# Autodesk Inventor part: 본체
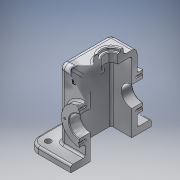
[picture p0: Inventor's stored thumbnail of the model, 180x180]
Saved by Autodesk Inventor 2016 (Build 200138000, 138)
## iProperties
Created: 2022-11
Part Number: 본체
Material: 알루미늄 6061
Document SubType Name: Modeling
Designer: CAD2
Density: 2.7 g/cm^3
Appearance: 알루미늄 - 평지
Mass: 1116.9 g
Surface Area: 1009.84 cm^2
Volume: 413.665 cm^3
Author: CAD2
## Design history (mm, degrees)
sketch "스케치1"
  geometry: L1 (-40, 40)-(40, 40); L2 (40, 40)-(40, -40); L3 (40, -40)-(-40, -40); L4 (-40, -40)-(-40, 40); L5 (-40, 40)-(40, -40); L6 (40, 40)-(-40, -40); 1 further point
  constraints: 12 end point, 2 midpoint, 2 parallel, 1 horizontal, 1 perpendicular
  dimensions: "d0" = 80 distance of L2.end L3.end; "d1" = 80 distance of L1.end L2.end
extrude "돌출1" new body sketch "스케치1" stored distance "d2" = 117; taper "d3" = 0 deg
fillet "모깎기1" dims "d4" = 8
fillet "모깎기2" dims "d5" = 8
feature "쉘1" dims "d6" = 8
fillet "모깎기3" dims "d11" = 3
fillet "모깎기4" dims "d12" = 3
sketch "스케치4"
  geometry: L1 (64, 0)-(0, 0) reference; C1 r 16 at (32, 55); 2 further points
  constraints: 1 centre point, 1 midpoint, 1 vertical alignment
  dimensions: "d13" = 32 diameter of C1; "d14" = 55 distance from line of L1 C1.centre
extrude "돌출3" cut sketch "스케치4" stored distance "d15" = 10; taper "d16" = 0 deg
sketch "스케치5"
  geometry: C1 r 16 at (32, 55) reference; C2 r 27.5 at (32, 55); 1 further point
  constraints: 1 centre point, 1 coincident
  dimensions: "d17" = 55 diameter of C2
extrude "돌출4" join sketch "스케치5" distance "d18" = 9; taper "d19" = 0 deg
sketch "스케치6"
  geometry: C1 r 16 at (32, -55) reference; C2 r 27.5 at (32, -55); 1 further point
  constraints: 1 centre point, 1 coincident
  dimensions: "d20" = 55 diameter of C2
extrude "돌출5" join sketch "스케치6" distance "d21" = 9; taper "d22" = 0 deg
sketch "스케치7"
  geometry: L1 (32, -54)-(-32, -54) reference; L2 (32, 55)-(32, -54) reference; L3 (-32, 55)-(32, 55) reference; L4 (-32, -54)-(-32, 55) reference; C1 r 27.5 at (0, 0) reference; 2 further points
  dimensions: "d23" = 22.5 distance of C1.centre point (0, -22.5)
hole "구멍1" sketch "스케치7" at (0, -22.5) diameter "d24" = 3.242; stored, may be unused: countersink angle "d28" = 90 deg, drill point angle "d30" = 118 deg; dims "d25" = 8, "d26" = 4, "d27" = 2, "d29" = 10
node "작업 평면1"
sketch "스케치8"
  geometry: L1 (-65, 62)-(65, 62); L2 (65, 62)-(65, -62); L3 (65, -62)-(-65, -62); L4 (-65, -62)-(-65, 62); L5 (-65, 62)-(65, -62); L6 (65, 62)-(-65, -62); 1 further point
  constraints: 12 end point, 2 midpoint, 2 parallel, 1 horizontal, 1 perpendicular
  dimensions: "d35" = 130 distance of L2.end L3.end; "d36" = 124 distance of L1.end L2.end
extrude "돌출6" join sketch "스케치8" distance "d37" = 10; taper "d38" = 0 deg
fillet "모깎기5" dims "d39" = 15
hole "구멍2" diameter "d42" = 9; stored, may be unused: countersink angle "d46" = 90 deg, drill point angle "d48" = 0 deg; dims "d40" = 10, "d41" = 10, "d43" = 8, "d44" = 4, "d45" = 2, "d47" = 10
hole "구멍3" diameter "d51" = 9; stored, may be unused: countersink angle "d55" = 90 deg, drill point angle "d57" = 0 deg; dims "d49" = 10, "d50" = 10, "d52" = 8, "d53" = 4, "d54" = 2, "d56" = 10
hole "구멍4" diameter "d60" = 9; stored, may be unused: countersink angle "d64" = 90 deg, drill point angle "d66" = 0 deg; dims "d58" = 10, "d59" = 10, "d61" = 8, "d62" = 4, "d63" = 2, "d65" = 10
hole "구멍5" diameter "d69" = 9; stored, may be unused: countersink angle "d73" = 90 deg, drill point angle "d75" = 0 deg; dims "d67" = 10, "d68" = 10, "d70" = 8, "d71" = 4, "d72" = 2, "d74" = 10
fillet "모깎기6" dims "d76" = 3
sketch "스케치10"
  geometry: L1 (-32, 29)-(-32, -29) reference; L2 (29, 32)-(-29, 32) reference; L3 (32, -29)-(32, 29) reference; L4 (-29, -32)-(29, -32) reference; A1 r 3 centre (-29, -29) between (-32, -29) and (-29, -32) reference; A2 r 3 centre (-29, 29) between (-29, 32) and (-32, 29) reference; A3 r 3 centre (29, 29) between (32, 29) and (29, 32) reference; A4 r 3 centre (29, -29) between (29, -32) and (32, -29) reference; 1 further point
extrude "돌출7" cut sketch "스케치10" distance "d77" = 10; taper "d78" = 0 deg
sketch "스케치11"
  geometry: L1 (-55, -48.5)-(-41.108, 30.285); L2 (-55, -48.5)-(-43.268, -48.5); 2 further points
  constraints: 4 end point, 1 horizontal
  dimensions: "d79" = 10 horizontal distance of point (-65, -58.5) L1.start; "d80" = 100 deg angle of L2 L1; "d81" = 80 distance of L1.start L1.end
feature "리브1" sketch "스케치11" dims "d82" = 1, "d83" = 10, "d84" = 0, "d85" = 0, "d86" = 1, "d87" = 1
fillet "모깎기7" dims "d90" = 3
fillet "모깎기8" dims "d91" = 3
fillet "모깎기9" dims "d92" = 3
fillet "모깎기10" dims "d93" = 3
fillet "모깎기11" dims "d94" = 3
chamfer "모따기1" distance "d95" = 1; stored, may be unused: second distance "d96" = 2, angle "d97" = 100 deg
sketch "스케치14"
  geometry: C1 r 20 at (0, 0); 1 further point
  constraints: 1 centre point, 1 coincident
  dimensions: "d100" = 40 diameter of C1
extrude "돌출8" join sketch "스케치14" distance "d101" = 10; taper "d102" = -10 deg
sketch "스케치16"
  geometry: C1 r 10.5 at (0, 0); 1 further point
  constraints: 1 centre point, 1 coincident
  dimensions: "d103" = 21 diameter of C1
extrude "돌출9" cut sketch "스케치16" stored distance "d104" = 10; taper "d105" = 0 deg
sketch "스케치17"
  geometry: C1 r 14 at (0, 0); 1 further point
  constraints: 1 centre point, 1 coincident
  dimensions: "d106" = 28 diameter of C1
extrude "돌출10" cut sketch "스케치17" distance "d107" = 4; taper "d108" = 0 deg
chamfer "모따기2" distance "d109" = 1; stored, may be unused: second distance "d110" = 2, angle "d111" = 100 deg
sketch "스케치21"
  geometry: L1 (13.763, 18)-(50.237, 18) reference; L2 (72, -96)-(72, 0) reference; 2 further points
  constraints: 1 other
  dimensions: "d112" = 25 distance from line of L1 point (32, -7); "d113" = 40 distance from line of L2 point (32, -7)
feature "엠보싱2" sketch "스케치21" dims "d114" = 0.5, "d115" = 0
fillet "모깎기12" dims "d116" = 3
feature "분할1"
node "솔리드1"
pattern_circular "원형 패턴1" dims angle "d32" = 360 deg
mirror "대칭1"
mirror "대칭2"
node "투영된 루프1"
node "투영된 루프2"
other parameters: "d34" = -58.5
